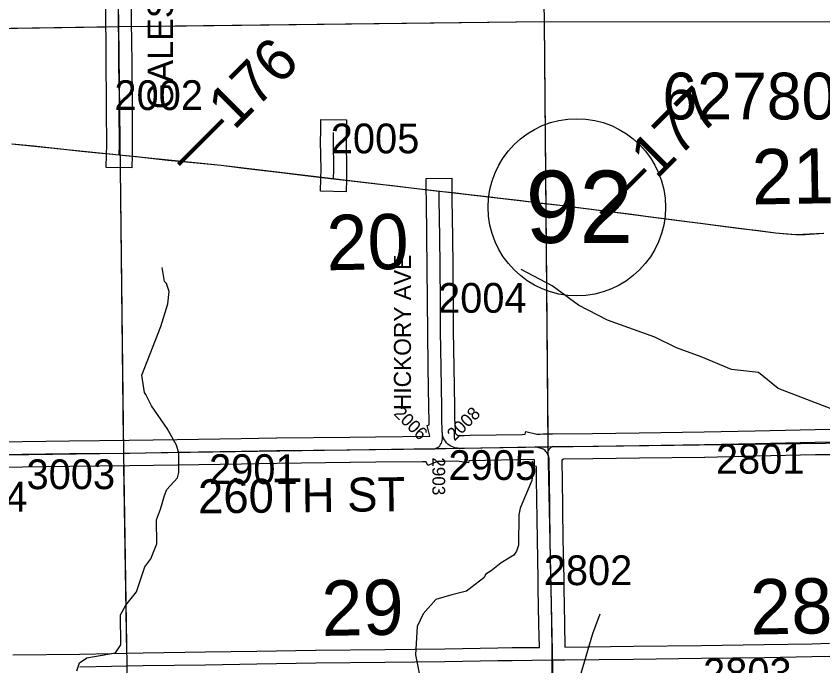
# Model space of a CAD drawing. Extents: x 23.6 to 68.7, y -63 to -29.
# Drawn here: x 39.457 to 41.355, y -50.14 to -48.611 of the extents above; entities that cross this region are included whole.
import ezdxf

# ---------------------------------------------------------------- set-up
doc = ezdxf.new("R2010")
doc.units = 0
for name, color, linetype in [('tdCoHydroRiver', 7, 'Continuous'), ('tdCoPriCL', 7, 'Continuous'), ('tdCoPrimary', 7, 'Continuous'), ('tdCoPriNonDiv', 7, 'Continuous'), ('tdCoPriNonDivCL', 7, 'Continuous'), ('tdCoSecRdNmbr', 7, 'Continuous'), ('tdCoSecRdTxt', 7, 'Continuous'), ('tdCoSecRteBand', 7, 'Continuous'), ('tdCoSecRteCL', 7, 'Continuous'), ('tdCoSectLine', 7, 'Continuous'), ('tdCoSectLinePart', 7, 'Continuous'), ('tdCoSectNmbr', 7, 'Continuous'), ('tdCoShieldStRte', 7, 'Continuous'), ('tdCoStrucPriMaintName', 7, 'Continuous'), ('tdCoSurfGravel', 7, 'Continuous'), ('tdStHwyPriRefPost1', 7, 'Continuous')]:
    doc.layers.add(name, color=color, linetype=linetype)

msp = doc.modelspace()

# ---------------------------------------------------------------- linework, layer by layer
at = {"layer": 'tdCoHydroRiver'}
for points in [[(39.5997, -50.1516), (39.6058, -50.1326), (39.623, -50.1214), (39.6908, -50.1097), (39.7033, -50.0906), (39.7026, -50.0196), (39.715, -49.9974), (39.74, -49.9656), (39.7599, -49.907), (39.774, -49.8879), (39.7878, -49.853), (39.7873, -49.7962), (39.7965, -49.7709), (39.8057, -49.7392), (39.8119, -49.7249), (39.8369, -49.6979), (39.8399, -49.6852), (39.8395, -49.6394), (39.8346, -49.6205), (39.8121, -49.5813), (39.7753, -49.528), (39.7624, -49.5013), (39.7592, -49.4966), (39.7525, -49.4556), (39.7972, -49.3415), (39.8141, -49.2877), (39.8169, -49.2592), (39.8104, -49.2403), (39.8057, -49.2357), (39.8006, -49.2026)], [(41.3744, -49.5349), (41.2493, -49.4871), (41.2031, -49.4497), (41.1399, -49.4424), (41.0686, -49.4131), (41.01, -49.3915), (40.9592, -49.3668), (40.8484, -49.3268), (40.7801, -49.2911), (40.7182, -49.2459), (40.6452, -49.2071)], [(40.67, -49.6584), (40.6748, -49.6662), (40.6704, -49.7042), (40.6426, -49.7691), (40.6396, -49.785), (40.6387, -49.856), (40.6341, -49.8702), (40.6279, -49.8798), (40.598, -49.8974), (40.5745, -49.9166), (40.562, -49.9246), (40.5573, -49.9325), (40.5166, -49.9645), (40.4819, -49.9727), (40.4442, -49.9841), (40.4145, -50.0176), (40.4006, -50.0477), (40.3965, -50.114), (40.4114, -50.1897)], [(40.8297, -50.0184), (40.8127, -50.0643), (40.7852, -50.1577), (40.7823, -50.1814), (40.7853, -50.3329), (40.7902, -50.3502), (40.8016, -50.3848), (40.8035, -50.4196), (40.7973, -50.4354), (40.7958, -50.4433), (40.7568, -50.491), (40.7475, -50.5085), (40.7365, -50.5165), (40.6829, -50.528), (40.6704, -50.5329), (40.6047, -50.603), (40.5798, -50.6395), (40.5691, -50.6744), (40.5503, -50.6872), (40.5298, -50.6889), (40.5188, -50.6938), (40.4846, -50.7478), (40.4564, -50.7733), (40.4296, -50.7814)]]:
    msp.add_lwpolyline(points, dxfattribs=at)
at = {"layer": 'tdCoPriCL'}
msp.add_lwpolyline([(39.4472, -48.9112), (39.4983, -48.9162), (39.5621, -48.9233), (39.6112, -48.9285), (39.6504, -48.9327), (39.6761, -48.9354), (39.6993, -48.9377), (39.7395, -48.9416), (39.7932, -48.9477), (39.8142, -48.9497), (39.8561, -48.9539), (39.8736, -48.9556), (39.939, -48.962), (39.987, -48.9682), (40.0263, -48.9729), (40.0741, -48.9785), (40.1308, -48.9855), (40.1695, -48.9899), (40.2035, -48.9938), (40.2386, -48.9978), (40.3054, -49.0057), (40.3419, -49.0099), (40.3861, -49.0153), (40.4317, -49.0205), (40.4515, -49.0226), (40.4849, -49.0261), (40.5153, -49.0296), (40.5718, -49.0365), (40.5959, -49.0392), (40.6386, -49.0444), (40.6923, -49.0508), (40.7013, -49.0519), (40.7429, -49.0567), (40.7848, -49.0619), (40.8465, -49.0703), (40.9047, -49.0774), (40.9431, -49.0826), (41.0161, -49.0917), (41.0726, -49.0991), (41.1246, -49.1058), (41.1678, -49.1112), (41.1968, -49.1148), (41.2092, -49.1164), (41.243, -49.1206), (41.2692, -49.1233), (41.28, -49.1241), (41.2909, -49.1247), (41.3018, -49.1249), (41.3128, -49.1247), (41.3237, -49.1243), (41.3562, -49.1221)], dxfattribs=at)
at = {"layer": 'tdCoPrimary'}
for points in [[(39.4476, -48.9112), (39.4987, -48.9162), (39.5625, -48.9233), (39.6116, -48.9285), (39.6508, -48.9327), (39.6765, -48.9354), (39.6997, -48.9377), (39.7398, -48.9416), (39.7936, -48.9477), (39.8146, -48.9497), (39.874, -48.9556), (39.9393, -48.962), (39.9874, -48.9682), (40.0266, -48.9729), (40.0745, -48.9785), (40.1312, -48.9855), (40.1699, -48.9899), (40.2039, -48.9938), (40.239, -48.9978), (40.3058, -49.0057), (40.3423, -49.0099), (40.3864, -49.0153), (40.4321, -49.0205), (40.4519, -49.0226), (40.4853, -49.0261), (40.5157, -49.0296), (40.5721, -49.0365), (40.5963, -49.0392), (40.639, -49.0444), (40.6927, -49.0508), (40.7433, -49.0567), (40.7852, -49.0619), (40.8469, -49.0703), (40.9051, -49.0774), (40.9435, -49.0826), (41.0165, -49.0917), (41.073, -49.0991), (41.125, -49.1058), (41.1682, -49.1112), (41.2096, -49.1164), (41.2434, -49.1206), (41.2695, -49.1233), (41.2804, -49.1241), (41.2913, -49.1247)], [(39.4476, -48.9112), (39.4987, -48.9162), (39.5625, -48.9233), (39.6116, -48.9285), (39.6508, -48.9327), (39.6765, -48.9354), (39.6997, -48.9377), (39.7398, -48.9416), (39.7936, -48.9477), (39.8146, -48.9497), (39.874, -48.9556), (39.9393, -48.962), (39.9874, -48.9682), (40.0266, -48.9729), (40.0745, -48.9785), (40.1312, -48.9855), (40.1699, -48.9899), (40.2039, -48.9938), (40.239, -48.9978), (40.3058, -49.0057), (40.3423, -49.0099), (40.3864, -49.0153), (40.4321, -49.0205), (40.4519, -49.0226), (40.4853, -49.0261), (40.5157, -49.0296), (40.5721, -49.0365), (40.5963, -49.0392), (40.639, -49.0444), (40.6927, -49.0508), (40.7433, -49.0567), (40.7852, -49.0619), (40.8469, -49.0703), (40.9051, -49.0774), (40.9435, -49.0826), (41.0165, -49.0917), (41.073, -49.0991), (41.125, -49.1058), (41.1682, -49.1112), (41.2096, -49.1164), (41.2434, -49.1206), (41.2695, -49.1233), (41.2804, -49.1241), (41.2913, -49.1247)], [(39.4476, -48.9112), (39.4987, -48.9162), (39.5625, -48.9233), (39.6116, -48.9285), (39.6508, -48.9327), (39.6765, -48.9354), (39.6997, -48.9377), (39.7398, -48.9416), (39.7936, -48.9477), (39.8146, -48.9497), (39.874, -48.9556), (39.9393, -48.962), (39.9874, -48.9682), (40.0266, -48.9729), (40.0745, -48.9785), (40.1312, -48.9855), (40.1699, -48.9899), (40.2039, -48.9938), (40.239, -48.9978), (40.3058, -49.0057), (40.3423, -49.0099), (40.3864, -49.0153), (40.4321, -49.0205), (40.4519, -49.0226), (40.4853, -49.0261), (40.5157, -49.0296), (40.5721, -49.0365), (40.5963, -49.0392), (40.639, -49.0444), (40.6927, -49.0508), (40.7433, -49.0567), (40.7852, -49.0619), (40.8469, -49.0703), (40.9051, -49.0774), (40.9435, -49.0826), (41.0165, -49.0917), (41.073, -49.0991), (41.125, -49.1058), (41.1682, -49.1112), (41.2096, -49.1164), (41.2434, -49.1206), (41.2695, -49.1233), (41.2804, -49.1241), (41.2913, -49.1247), (41.3022, -49.1249), (41.3131, -49.1247), (41.324, -49.1243), (41.3566, -49.1221)], [(41.2913, -49.1247), (41.2913, -49.1247), (41.3022, -49.1249), (41.3131, -49.1247), (41.324, -49.1243), (41.3566, -49.1221)], [(41.2913, -49.1247), (41.2913, -49.1247), (41.3022, -49.1249), (41.3131, -49.1247), (41.324, -49.1243), (41.3566, -49.1221)]]:
    msp.add_lwpolyline(points, dxfattribs=at)
at = {"layer": 'tdCoPriNonDiv'}
msp.add_lwpolyline([(39.4473, -48.9112), (39.6761, -48.9354), (39.939, -48.962), (40.3861, -49.0153), (40.7429, -49.0567), (41.2431, -49.1206), (41.291, -49.1247), (41.3562, -49.1221)], dxfattribs=at)
at = {"layer": 'tdCoPriNonDivCL'}
msp.add_lwpolyline([(39.4472, -48.9112), (39.4983, -48.9162), (39.5621, -48.9233), (39.6112, -48.9285), (39.6504, -48.9327), (39.6761, -48.9354), (39.6993, -48.9377), (39.7395, -48.9416), (39.7932, -48.9477), (39.8142, -48.9497), (39.8736, -48.9556), (39.939, -48.962), (39.987, -48.9682), (40.0263, -48.9729), (40.0741, -48.9785), (40.1308, -48.9855), (40.1695, -48.9899), (40.2035, -48.9938), (40.2386, -48.9978), (40.3054, -49.0057), (40.3419, -49.0099), (40.3861, -49.0153), (40.4317, -49.0205), (40.4515, -49.0226), (40.4849, -49.0261), (40.5153, -49.0296), (40.5718, -49.0365), (40.5959, -49.0392), (40.6386, -49.0444), (40.6923, -49.0508), (40.7429, -49.0567), (40.7848, -49.0619), (40.8465, -49.0703), (40.9047, -49.0774), (40.9431, -49.0826), (41.0161, -49.0917), (41.0726, -49.0991), (41.1246, -49.1058), (41.1678, -49.1112), (41.2092, -49.1164), (41.243, -49.1206), (41.2692, -49.1233), (41.28, -49.1241), (41.2909, -49.1247), (41.2909, -49.1247), (41.3018, -49.1249), (41.3128, -49.1247), (41.3237, -49.1243), (41.3562, -49.1221)], dxfattribs=at)
msp.add_lwpolyline([(39.4472, -48.9112), (39.4983, -48.9162), (39.5621, -48.9233), (39.6112, -48.9285), (39.6504, -48.9327), (39.6761, -48.9354), (39.6993, -48.9377), (39.7395, -48.9416), (39.7932, -48.9477), (39.8142, -48.9497), (39.8736, -48.9556), (39.939, -48.962), (39.987, -48.9682), (40.0263, -48.9729), (40.0741, -48.9785), (40.1308, -48.9855), (40.1695, -48.9899), (40.2035, -48.9938), (40.2386, -48.9978), (40.3054, -49.0057), (40.3419, -49.0099), (40.3861, -49.0153), (40.4317, -49.0205), (40.4515, -49.0226), (40.4849, -49.0261), (40.5153, -49.0296), (40.5718, -49.0365), (40.5959, -49.0392), (40.6386, -49.0444), (40.6923, -49.0508), (40.7429, -49.0567), (40.7848, -49.0619), (40.8465, -49.0703), (40.9047, -49.0774), (40.9431, -49.0826), (41.0161, -49.0917), (41.0726, -49.0991), (41.1246, -49.1058), (41.1678, -49.1112), (41.2092, -49.1164), (41.243, -49.1206), (41.2692, -49.1233), (41.28, -49.1241), (41.2909, -49.1247), (41.2909, -49.1247), (41.3018, -49.1249), (41.3128, -49.1247), (41.3237, -49.1243), (41.3562, -49.1221)], dxfattribs=at)
at = {"layer": 'tdCoSecRteBand'}
for points in [[(39.7273, -48.5468), (39.7279, -48.6334), (39.7286, -48.6628), (39.7286, -48.663), (39.7286, -48.6633), (39.7289, -48.7265), (39.7299, -48.8035), (39.7299, -48.8038), (39.7299, -48.8041), (39.7296, -48.8319), (39.7301, -48.9138), (39.7301, -48.9141), (39.7301, -48.9145), (39.7297, -48.9382), (39.7291, -48.9682), (39.6691, -48.967), (39.6697, -48.9371), (39.6701, -48.9137), (39.6696, -48.832), (39.6696, -48.8318), (39.6696, -48.8316), (39.6699, -48.8039), (39.6689, -48.7271), (39.6689, -48.727), (39.6689, -48.7269), (39.6686, -48.6639), (39.6679, -48.6345), (39.6679, -48.6343), (39.6679, -48.6341), (39.6673, -48.5473)], [(40.2332, -49.0245), (40.1732, -49.0231), (40.1739, -48.9931), (40.1744, -48.9721), (40.1732, -48.9049), (40.1732, -48.9044), (40.1732, -48.9039), (40.1735, -48.8843), (40.1739, -48.8543), (40.2339, -48.8552), (40.2335, -48.8852), (40.2332, -48.9043), (40.2344, -48.9716), (40.2344, -48.9722), (40.2344, -48.9729), (40.2339, -48.9945), (40.2332, -49.0245)], [(39.4145, -49.6129), (39.5825, -49.6105), (39.5825, -49.6105), (39.5826, -49.6105), (39.7231, -49.6091), (39.8356, -49.6075), (39.9864, -49.6051), (40.0697, -49.6035), (40.0698, -49.6035), (40.0699, -49.6035), (40.2417, -49.6017), (40.3023, -49.601), (40.3023, -49.601), (40.3023, -49.601), (40.43, -49.5996), (40.4236, -49.574), (40.4286, -49.5728), (40.4283, -49.5646), (40.4283, -49.5644), (40.4283, -49.5641), (40.428, -49.5313), (40.4265, -49.438), (40.4265, -49.438), (40.4265, -49.438), (40.4254, -49.3526), (40.4254, -49.3525), (40.4254, -49.3524), (40.4249, -49.2844), (40.4241, -49.2001), (40.4233, -49.1318), (40.422, -49.0421), (40.422, -49.042), (40.422, -49.0419), (40.4219, -49.0228), (40.4217, -48.9928), (40.4817, -48.9924), (40.4819, -49.0224), (40.482, -49.0414), (40.4833, -49.131), (40.4833, -49.1311), (40.4833, -49.1311), (40.4841, -49.1995), (40.4841, -49.1995), (40.4841, -49.1995), (40.4849, -49.2839), (40.4849, -49.2839), (40.4849, -49.284), (40.4854, -49.3519), (40.4865, -49.4371), (40.488, -49.5305), (40.488, -49.5306), (40.488, -49.5306), (40.4883, -49.5633), (40.4884, -49.5645), (40.4886, -49.5645), (40.4899, -49.5913), (40.4902, -49.5922), (40.4906, -49.5931), (40.4912, -49.594), (40.4919, -49.5949), (40.4927, -49.5957), (40.4935, -49.5963), (40.4944, -49.5969), (40.4954, -49.5974), (40.4964, -49.5978), (40.4974, -49.598), (40.4976, -49.5981), (40.5108, -49.5978), (40.5109, -49.5978), (40.5109, -49.5978), (40.5251, -49.5974), (40.5251, -49.5975), (40.6476, -49.5952), (40.6545, -49.5951), (40.6561, -49.5885), (40.6815, -49.5946), (40.6886, -49.5945), (40.6886, -49.5944), (40.6965, -49.5943), (40.7076, -49.5941), (40.7076, -49.5942), (40.7186, -49.5941), (40.8129, -49.5931), (40.9226, -49.5915), (40.9227, -49.5915), (40.9227, -49.5915), (41.0756, -49.5893), (41.1957, -49.5866), (41.3361, -49.5834), (41.3365, -49.5834), (41.3368, -49.5834), (41.4886, -49.5832)], [(39.4493, -50.1137), (39.6067, -50.1122), (39.7555, -50.1093), (39.7556, -50.1093), (39.7557, -50.1093), (39.9022, -50.1073), (40.0229, -50.1057), (40.1614, -50.1029), (40.1616, -50.1029), (40.1617, -50.1029), (40.3239, -50.1015), (40.4652, -50.0997), (40.5897, -50.0976), (40.5898, -50.0976), (40.5898, -50.0976), (40.6235, -50.0971), (40.6236, -50.0971), (40.6237, -50.0971), (40.6878, -50.0965), (40.6868, -50.0416), (40.6852, -49.958), (40.6852, -49.9578), (40.6852, -49.9576), (40.685, -49.9362), (40.6832, -49.8429), (40.6832, -49.8428), (40.6832, -49.8427), (40.6814, -49.6999), (40.6809, -49.6705), (40.676, -49.6703), (40.6766, -49.6552), (40.6749, -49.6547), (40.5219, -49.6576), (40.5213, -49.6621), (40.494, -49.6582), (40.4665, -49.6588), (40.4481, -49.6593), (40.4252, -49.6683), (40.4219, -49.6599), (40.4128, -49.6601), (40.4128, -49.6598), (40.303, -49.661), (40.2424, -49.6617), (40.2423, -49.6617), (40.2423, -49.6617), (40.0707, -49.6635), (39.9875, -49.6651), (39.9874, -49.6651), (39.9874, -49.6651), (39.8365, -49.6675), (39.8365, -49.6675), (39.8364, -49.6675), (39.7239, -49.6691), (39.7239, -49.6691), (39.7238, -49.6691), (39.5832, -49.6705), (39.4153, -49.6729)], [(41.4888, -49.6432), (41.3372, -49.6434), (41.1971, -49.6466), (41.1971, -49.6466), (41.1971, -49.6466), (41.0768, -49.6493), (41.0767, -49.6493), (41.0765, -49.6493), (40.9235, -49.6515), (40.8137, -49.6531), (40.8136, -49.6531), (40.8136, -49.6531), (40.7446, -49.6538), (40.7406, -49.6562), (40.7408, -49.6628), (40.7408, -49.663), (40.7408, -49.6631), (40.7414, -49.6989), (40.7414, -49.699), (40.7414, -49.699), (40.7432, -49.8418), (40.745, -49.9353), (40.745, -49.9354), (40.745, -49.9356), (40.7452, -49.957), (40.7468, -50.0405), (40.7468, -50.0405), (40.7468, -50.0405), (40.7478, -50.0959), (40.9088, -50.094), (41.068, -50.092), (41.2168, -50.09), (41.3283, -50.0879), (41.3701, -50.0869)]]:
    msp.add_lwpolyline(points, dxfattribs=at)
at = {"layer": 'tdCoSecRteCL'}
msp.add_line((40.4421, -49.6294), (40.4958, -49.6281), dxfattribs=at)
for points in [[(39.6997, -48.9377), (39.7001, -48.9139), (39.6996, -48.8318), (39.6999, -48.8038), (39.6989, -48.7267), (39.6986, -48.6634), (39.6979, -48.6339), (39.6973, -48.547), (39.6968, -48.4716), (39.6966, -48.3779), (39.6956, -48.2978), (39.6938, -48.2316), (39.6926, -48.1521), (39.6926, -48.139)], [(40.2039, -48.9938), (40.2044, -48.9721), (40.2032, -48.9043), (40.2035, -48.8848)], [(40.46, -49.5958), (40.4596, -49.5928), (40.4593, -49.5898), (40.4588, -49.5826), (40.4583, -49.5638), (40.458, -49.5309), (40.4565, -49.4376), (40.4554, -49.3522), (40.4549, -49.2842), (40.4541, -49.1998), (40.4533, -49.1314), (40.452, -49.0417), (40.4519, -49.0226)], [(40.4421, -49.6294), (40.4453, -49.6281), (40.4483, -49.6264), (40.451, -49.6244), (40.4534, -49.6219), (40.4555, -49.6192), (40.4572, -49.6162), (40.4585, -49.613), (40.4593, -49.6097), (40.46, -49.6051), (40.4602, -49.6005), (40.46, -49.5958)], [(40.4958, -49.6281), (40.4916, -49.6275), (40.4874, -49.6264), (40.4834, -49.6249), (40.4795, -49.623), (40.4759, -49.6207), (40.4725, -49.618), (40.4695, -49.6149), (40.4668, -49.6115), (40.4645, -49.6079), (40.4626, -49.6041), (40.4611, -49.6), (40.46, -49.5958)], [(40.719, -49.6241), (40.8133, -49.6231), (40.9231, -49.6215), (41.0761, -49.6193), (41.1964, -49.6166), (41.3368, -49.6134), (41.4888, -49.6132), (41.5565, -49.6126), (41.6638, -49.6108), (41.7642, -49.611), (41.936, -49.6089), (42.1166, -49.6081), (42.2386, -49.6065), (42.3303, -49.6045), (42.3421, -49.6047), (42.3426, -49.6047)], [(39.3622, -49.6436), (39.4149, -49.6429), (39.5829, -49.6405), (39.7235, -49.6391), (39.836, -49.6375), (39.9869, -49.6351), (40.0702, -49.6335), (40.242, -49.6317), (40.3027, -49.631), (40.4354, -49.6296), (40.4421, -49.6294)], [(40.4958, -49.6281), (40.5115, -49.6278), (40.6782, -49.6247)], [(40.6782, -49.6247), (40.697, -49.6243), (40.719, -49.6241)], [(40.7072, -49.6415), (40.7052, -49.6382), (40.7033, -49.6358), (40.7012, -49.6335), (40.699, -49.6315), (40.6965, -49.6298), (40.6894, -49.6274), (40.6782, -49.6247)], [(40.719, -49.6241), (40.7164, -49.6252), (40.714, -49.6268), (40.712, -49.6286), (40.7102, -49.6308), (40.7088, -49.6333), (40.7078, -49.6359), (40.7073, -49.6387), (40.7072, -49.6415)], [(40.7178, -50.1262), (40.718, -50.1058), (40.7168, -50.0411), (40.7152, -49.9574), (40.715, -49.9358), (40.7132, -49.8423), (40.7114, -49.6994), (40.7108, -49.6636), (40.7105, -49.6516), (40.7097, -49.6481), (40.7086, -49.6447), (40.7072, -49.6415)], [(40.7178, -50.1262), (40.7476, -50.1259), (40.9092, -50.124), (41.0683, -50.122), (41.2173, -50.12), (41.3289, -50.1179), (41.3709, -50.1169), (41.5029, -50.1146), (41.5293, -50.1138), (41.6768, -50.1113), (41.7184, -50.1114), (41.8185, -50.1115), (41.8338, -50.1128), (41.8608, -50.1137)], [(39.6071, -50.1422), (39.7561, -50.1393), (39.9026, -50.1373), (40.0234, -50.1356), (40.162, -50.1329), (40.3243, -50.1315), (40.4656, -50.1297), (40.5903, -50.1276), (40.624, -50.1271), (40.7178, -50.1262)], [(40.7307, -50.7924), (40.7303, -50.7764), (40.7308, -50.7317), (40.7292, -50.6446), (40.7293, -50.6301), (40.7265, -50.5333), (40.7242, -50.4489), (40.7226, -50.3342), (40.7223, -50.3237), (40.72, -50.2273), (40.7177, -50.1459), (40.7178, -50.1262)]]:
    msp.add_lwpolyline(points, dxfattribs=at)
at = {"layer": 'tdCoSectLine'}
for points in [[(40.681, -47.6218), (40.6989, -48.6234)], [(39.6841, -47.6326), (39.6976, -48.6357)], [(39.6976, -48.6357), (40.6989, -48.6234)], [(40.6989, -48.6234), (40.7079, -49.6245)], [(40.6989, -48.6234), (41.7101, -48.6246)], [(38.7331, -48.6502), (39.6976, -48.6357)], [(39.6976, -48.6357), (39.7093, -49.6392)], [(40.7079, -49.6245), (41.7173, -49.6109)], [(38.7634, -49.6525), (39.7093, -49.6392)], [(39.7093, -49.6392), (40.7079, -49.6245)], [(39.7093, -49.6392), (39.7253, -50.6386)], [(40.7079, -49.6245), (40.7288, -50.6241)]]:
    msp.add_lwpolyline(points, dxfattribs=at)
at = {"layer": 'tdCoSectLinePart'}
for points in [[(40.6905, -48.1528), (40.6989, -48.6234)], [(39.7282, -48.6353), (40.6989, -48.6234)], [(40.6989, -48.6234), (41.7101, -48.6246)], [(40.6989, -48.6234), (40.7077, -49.5947)], [(38.7331, -48.6502), (39.6683, -48.6362)], [(39.7015, -48.9677), (39.709, -49.6089)], [(39.7098, -49.6688), (39.7168, -50.1104)]]:
    msp.add_lwpolyline(points, dxfattribs=at)
at = {"layer": 'tdCoShieldStRte'}
msp.add_circle((40.7759, -49.0608), 0.2085, dxfattribs=at)
at = {"layer": 'tdCoSurfGravel'}
for points in [[(39.6997, -48.9377), (39.7001, -48.9139), (39.6996, -48.8318), (39.6999, -48.8038), (39.6989, -48.7267), (39.6986, -48.6634), (39.6979, -48.6339), (39.6973, -48.547), (39.6968, -48.4716), (39.6966, -48.3779), (39.6956, -48.2978), (39.6938, -48.2316), (39.6926, -48.1521), (39.6926, -48.139)], [(40.2039, -48.9938), (40.2044, -48.9721), (40.2032, -48.9043), (40.2035, -48.8848)], [(40.4958, -49.6281), (40.4916, -49.6275), (40.4874, -49.6264), (40.4834, -49.6249), (40.4795, -49.623), (40.4759, -49.6207), (40.4725, -49.618), (40.4695, -49.6149), (40.4668, -49.6115), (40.4645, -49.6079), (40.4626, -49.6041), (40.4611, -49.6), (40.46, -49.5958), (40.4596, -49.5928), (40.4593, -49.5898), (40.4588, -49.5826), (40.4583, -49.5638), (40.458, -49.5309), (40.4565, -49.4376), (40.4554, -49.3522), (40.4549, -49.2842), (40.4541, -49.1998), (40.4533, -49.1314), (40.452, -49.0417), (40.4519, -49.0226)], [(40.4421, -49.6294), (40.4453, -49.6281), (40.4483, -49.6264), (40.451, -49.6244), (40.4534, -49.6219), (40.4555, -49.6192), (40.4572, -49.6162), (40.4585, -49.613), (40.4593, -49.6097), (40.46, -49.6051), (40.4602, -49.6005), (40.46, -49.5958)], [(39.4149, -49.6429), (39.5829, -49.6405), (39.7235, -49.6391), (39.836, -49.6375), (39.9869, -49.6351), (40.0702, -49.6335), (40.242, -49.6317), (40.3027, -49.631), (40.4354, -49.6296), (40.4421, -49.6294), (40.4958, -49.6281), (40.5115, -49.6278), (40.6782, -49.6247), (40.697, -49.6243), (40.719, -49.6241), (40.8133, -49.6231), (40.9231, -49.6215), (41.0761, -49.6193), (41.1964, -49.6166), (41.3368, -49.6134), (41.4888, -49.6132)], [(40.7177, -50.1459), (40.7178, -50.1262), (40.718, -50.1058), (40.7168, -50.0411), (40.7152, -49.9574), (40.715, -49.9358), (40.7132, -49.8423), (40.7114, -49.6994), (40.7108, -49.6636), (40.7105, -49.6516), (40.7097, -49.6481), (40.7086, -49.6447), (40.7072, -49.6415), (40.7052, -49.6382), (40.7033, -49.6358), (40.7012, -49.6335), (40.699, -49.6315), (40.6965, -49.6298), (40.6894, -49.6274), (40.6782, -49.6247)], [(40.719, -49.6241), (40.7164, -49.6252), (40.714, -49.6268), (40.712, -49.6286), (40.7102, -49.6308), (40.7088, -49.6333), (40.7078, -49.6359), (40.7073, -49.6387), (40.7072, -49.6415)], [(39.6071, -50.1422), (39.7561, -50.1393), (39.9026, -50.1373), (40.0234, -50.1356), (40.162, -50.1329), (40.3243, -50.1315), (40.4656, -50.1297), (40.5903, -50.1276), (40.624, -50.1271), (40.7178, -50.1262), (40.7476, -50.1259), (40.9092, -50.124), (41.0683, -50.122), (41.2173, -50.12), (41.3289, -50.1179), (41.3709, -50.1169), (41.5029, -50.1146), (41.5293, -50.1138), (41.6768, -50.1113), (41.7184, -50.1114)]]:
    msp.add_lwpolyline(points, dxfattribs=at)

# ---------------------------------------------------------------- texts
at = {"layer": 'tdCoSecRdNmbr'}
for s, height, rotation, p in [('2002', 0.07, 0.0311, (39.6883, -48.832)), ('2005', 0.07, 0.0315, (40.1972, -48.9339)), ('2004', 0.07, 0.0317, (40.4495, -49.3091)), ('2006', 0.03, 315.0308, (40.3433, -49.5479)), ('2008', 0.03, 45.0303, (40.4882, -49.6121)), ('2801', 0.07, 0.0322, (41.1031, -49.688)), ('2905', 0.07, 0.0317, (40.474, -49.7026)), ('3003', 0.07, 0.0307, (39.4816, -49.7242)), ('2901', 0.07, 0.0313, (39.9108, -49.7121)), ('2903', 0.03, 270.0294, (40.4361, -49.6494)), ('3004', 0.07, 0.031, (39.2755, -49.7769)), ('2802', 0.07, 0.0319, (40.6981, -49.9501)), ('2803', 0.07, 0.0322, (41.0729, -50.1919))]:
    msp.add_text(s, height=height, rotation=rotation, dxfattribs=at).set_placement(p)
at = {"layer": 'tdCoSecRdTxt'}
for s, height, rotation, p in [('GALESTON AVE', 0.06, 90, (39.8262, -48.8299)), ('HICKORY AVE', 0.04, 90, (40.3857, -49.5381)), ('260TH ST', 0.08, 0.6532, (39.8853, -49.7813))]:
    msp.add_text(s, height=height, rotation=rotation, dxfattribs=at).set_placement(p)
at = {"layer": 'tdCoSectNmbr'}
for s, rotation, p in [('21', 1.0322, (41.1884, -49.0545)), ('20', 1.0315, (40.1879, -49.2092)), ('29', 1.0315, (40.1764, -50.0697)), ('28', 1.0322, (41.1844, -50.0666))]:
    msp.add_text(s, height=0.13, rotation=rotation, dxfattribs=at).set_placement(p)
at = {"layer": 'tdCoShieldStRte'}
msp.add_text('92', height=0.17, dxfattribs=at).set_placement((40.6553, -49.1447))
at = {"layer": 'tdCoStrucPriMaintName'}
msp.add_text('62780S092', height=0.11, dxfattribs=at).set_placement((40.9772, -48.8541))
msp.add_text('62780S092', height=0.11, dxfattribs=at).set_placement((40.9772, -48.8541))
msp.add_text('62780S092', height=0.11, dxfattribs=at).set_placement((40.9772, -48.8541))
at = {"layer": 'tdStHwyPriRefPost1'}
for s, p in [('‒‒176', (39.8646, -48.9865)), ('‒‒177', (40.8585, -49.1025))]:
    msp.add_text(s, height=0.1, rotation=45, dxfattribs=at).set_placement(p)

doc.saveas('drawing.dxf')
